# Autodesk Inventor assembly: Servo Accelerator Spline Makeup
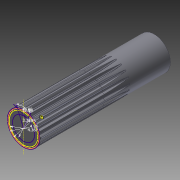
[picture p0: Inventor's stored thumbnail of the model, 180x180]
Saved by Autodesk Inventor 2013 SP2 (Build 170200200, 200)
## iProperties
Created: 2020-02
Part Number: Servo Accelerator Spline Makeup
Document SubType Name: Assembly
Designer: DELL
Author: DELL
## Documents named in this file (3)
- C:\Users\DELL\Dropbox\Inventor\Projects\Quadcopter F450\Assemblies\Servo - Design Accelerator Spline Tutorial.iam
- C:\Users\DELL\Dropbox\Inventor\Projects\Quadcopter F450\Shaft Test.ipt
- C:\Users\DELL\Dropbox\Inventor\Projects\Quadcopter F450\Assemblies\Servo - Design Accelerator Spline Tutorial\Design Accelerator\Involute Spline Connection2.iam
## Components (2 placed, 2 different names)
1. Shaft Test:1
2. Involute Spline Connection:1 [sub-assembly]
